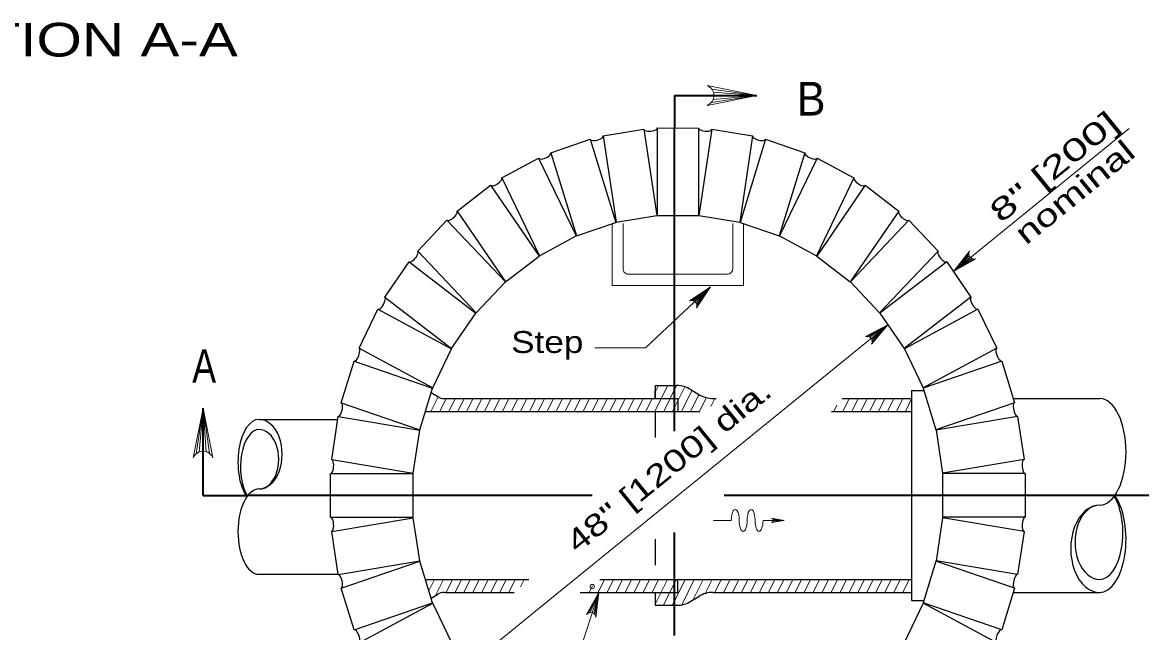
# Model space of a CAD drawing. Extents: x 1083.1 to 1117.1, y 697.4 to 741.4.
# Drawn here: x 1090.06 to 1098.04, y 723.17 to 727.52 of the extents above; entities that cross this region are included whole.
import ezdxf
from ezdxf.enums import TextEntityAlignment as Align

# ---------------------------------------------------------------- set-up
doc = ezdxf.new("R2010")
doc.units = 0
doc.header["$LTSCALE"] = 0.062
doc.header["$PDMODE"] = 32
doc.header["$PDSIZE"] = 0.031
doc.linetypes.add('MEDIUM_DASHED', pattern=[4.5, 3, -1.5])
doc.layers.add('1', color=7, linetype='Continuous', lineweight=13)

msp = doc.modelspace()

# ---------------------------------------------------------------- linework, layer by layer
at = {"layer": '1', "lineweight": 35}
for p, q in [((1094.71067, 727.00183), (1095.298, 727.00183)), ((1094.71067, 727.00183), (1094.71067, 726.76967)), ((1094.71067, 725.25758), (1094.71067, 726.76967)), ((1094.71067, 724.60558), (1094.71067, 725.25758)), ((1091.34783, 724.14683), (1091.34783, 724.76867)), ((1091.34783, 724.14683), (1091.66758, 724.14683)), ((1094.1245, 724.14683), (1091.66758, 724.14683)), ((1097.85225, 724.14683), (1095.0655, 724.14683)), ((1098.167, 724.14683), (1097.85225, 724.14683)), ((1094.71067, 723.14725), (1094.71067, 723.88192))]:
    msp.add_line(p, q, dxfattribs=at)
at = {"layer": '1'}
for p, q in [((1094.97367, 726.95225), (1095.298, 727.00183)), ((1094.9775, 727.04667), (1095.298, 727.00183)), ((1094.986, 726.97308), (1095.298, 727.00183)), ((1094.98833, 727.0245), (1095.298, 727.00183)), ((1094.99167, 727.00183), (1095.298, 727.00183)), ((1097.95358, 726.76517), (1096.70342, 725.74808)), ((1094.267, 725.64442), (1094.267, 726.08758)), ((1094.34383, 725.76575), (1094.34383, 726.08758)), ((1095.12658, 725.76575), (1095.12658, 726.08758)), ((1095.2035, 725.64442), (1095.2035, 726.08758)), ((1096.81108, 725.86867), (1096.70317, 725.74808)), ((1096.81408, 725.85667), (1096.70317, 725.74808)), ((1096.82017, 725.84692), (1096.70317, 725.74808)), ((1096.83158, 725.83775), (1096.70317, 725.74808)), ((1096.843, 725.83375), (1096.70317, 725.74808)), ((1094.38158, 725.72575), (1095.08883, 725.72575)), ((1094.267, 725.64442), (1095.2035, 725.64442)), ((1094.83525, 725.53908), (1094.96783, 725.63575)), ((1094.84692, 725.53608), (1094.96783, 725.63575)), ((1094.85908, 725.52783), (1094.96783, 725.63575)), ((1094.86592, 725.51858), (1094.96783, 725.63575)), ((1094.86983, 725.50692), (1094.96783, 725.63575)), ((1096.23242, 725.36483), (1095.51958, 724.78492)), ((1096.091, 725.28175), (1096.23242, 725.36483)), ((1096.10233, 725.27758), (1096.23242, 725.36483)), ((1096.11358, 725.26817), (1096.23242, 725.36483)), ((1096.11942, 725.25833), (1096.23242, 725.36483)), ((1096.12225, 725.24633), (1096.23242, 725.36483)), ((1094.66, 724.92983), (1094.56975, 724.74675)), ((1094.5965, 724.9305), (1094.57342, 724.88375)), ((1094.72458, 724.93125), (1094.63367, 724.74675)), ((1094.78417, 724.92242), (1094.69758, 724.74675)), ((1093.024, 724.851), (1092.97267, 724.74675)), ((1093.08192, 724.83883), (1093.03658, 724.74675)), ((1093.14583, 724.83883), (1093.10042, 724.74675)), ((1093.20975, 724.83883), (1093.16433, 724.74675)), ((1093.27358, 724.83883), (1093.22817, 724.74675)), ((1093.3375, 724.83883), (1093.29208, 724.74675)), ((1093.40133, 724.83883), (1093.356, 724.74675)), ((1093.46525, 724.83883), (1093.41983, 724.74675)), ((1093.52917, 724.83883), (1093.48375, 724.74675)), ((1093.593, 724.83883), (1093.54758, 724.74675)), ((1093.65692, 724.83883), (1093.6115, 724.74675)), ((1093.72083, 724.83883), (1093.67542, 724.74675)), ((1093.78467, 724.83883), (1093.73925, 724.74675)), ((1093.84858, 724.83883), (1093.80317, 724.74675)), ((1093.91242, 724.83883), (1093.86708, 724.74675)), ((1093.97633, 724.83883), (1093.93092, 724.74675)), ((1094.04025, 724.83883), (1093.99483, 724.74675)), ((1094.10408, 724.83883), (1094.05867, 724.74675)), ((1094.168, 724.83883), (1094.12258, 724.74675)), ((1094.23192, 724.83883), (1094.1865, 724.74675)), ((1094.29575, 724.83883), (1094.25033, 724.74675)), ((1094.35967, 724.83883), (1094.31425, 724.74675)), ((1094.4235, 724.83883), (1094.37817, 724.74675)), ((1094.48742, 724.83883), (1094.442, 724.74675)), ((1094.55133, 724.83883), (1094.50592, 724.74675)), ((1094.8355, 724.89708), (1094.76142, 724.74675)), ((1094.88492, 724.86767), (1094.82533, 724.74675)), ((1094.93742, 724.8445), (1094.88917, 724.74675)), ((1094.9985, 724.83883), (1094.9705, 724.78208)), ((1095.95675, 724.83883), (1095.91133, 724.74675)), ((1096.02067, 724.83883), (1095.97525, 724.74675)), ((1096.0845, 724.83883), (1096.03917, 724.74667)), ((1096.14842, 724.83883), (1096.103, 724.74667)), ((1096.21233, 724.83883), (1096.16692, 724.74675)), ((1096.27617, 724.83883), (1096.23075, 724.74675)), ((1096.34008, 724.83883), (1096.29467, 724.74675)), ((1096.40283, 724.8365), (1096.35858, 724.74675)), ((1091.29825, 724.44442), (1091.34783, 724.76867)), ((1091.319, 724.45667), (1091.34783, 724.76867)), ((1091.34783, 724.46233), (1091.34783, 724.76867)), ((1091.3705, 724.459), (1091.34783, 724.76867)), ((1091.39267, 724.44817), (1091.34783, 724.76867)), ((1095.51958, 724.78492), (1093.71942, 723.32042)), ((1095.86925, 724.791), (1095.8475, 724.74675)), ((1095.11617, 723.96858), (1094.99, 723.96858)), ((1095.49275, 723.96858), (1095.34233, 723.96858)), ((1095.49275, 723.96858), (1095.40208, 723.98458)), ((1095.49275, 723.96858), (1095.40208, 723.95258)), ((1095.49275, 723.96858), (1095.41175, 723.95858)), ((1095.49275, 723.96858), (1095.412, 723.97825)), ((1095.49275, 723.96858), (1095.41217, 723.97825)), ((1095.49275, 723.96858), (1095.41442, 723.97292)), ((1095.41458, 723.96475), (1095.49117, 723.96833)), ((1092.95892, 723.466), (1092.99883, 723.547)), ((1093.00583, 723.43158), (1093.06275, 723.547)), ((1093.08117, 723.45483), (1093.12658, 723.547)), ((1093.14508, 723.45483), (1093.1905, 723.547)), ((1093.209, 723.45483), (1093.25433, 723.547)), ((1093.27283, 723.45483), (1093.31825, 723.547)), ((1093.33675, 723.45483), (1093.38217, 723.547)), ((1093.40067, 723.45483), (1093.446, 723.547)), ((1093.4645, 723.45483), (1093.50992, 723.547)), ((1093.52842, 723.45483), (1093.57383, 723.547)), ((1093.61175, 723.49433), (1093.63767, 723.547)), ((1094.10333, 723.45483), (1094.12375, 723.49617)), ((1094.16725, 723.45483), (1094.21267, 723.547)), ((1094.23117, 723.45483), (1094.2765, 723.547)), ((1094.295, 723.45483), (1094.34042, 723.547)), ((1094.35892, 723.45483), (1094.40433, 723.547)), ((1094.42275, 723.45483), (1094.46817, 723.547)), ((1094.48667, 723.45483), (1094.53208, 723.547)), ((1094.55058, 723.45483), (1094.59592, 723.547)), ((1094.57317, 723.37117), (1094.65983, 723.547)), ((1094.63317, 723.36317), (1094.72375, 723.547)), ((1094.69683, 723.36283), (1094.78758, 723.547)), ((1094.76283, 723.36708), (1094.8515, 723.547)), ((1094.84442, 723.403), (1094.91542, 723.547)), ((1094.93208, 723.45125), (1094.97925, 723.547)), ((1094.99775, 723.45483), (1095.04317, 723.547)), ((1095.06167, 723.45483), (1095.107, 723.547)), ((1095.1255, 723.45483), (1095.17092, 723.547)), ((1095.18942, 723.45483), (1095.23483, 723.547)), ((1095.25333, 723.45483), (1095.29867, 723.547)), ((1095.31717, 723.45483), (1095.36258, 723.547)), ((1095.38108, 723.45483), (1095.4265, 723.547)), ((1095.44492, 723.45483), (1095.49033, 723.547)), ((1095.50883, 723.45483), (1095.55425, 723.547)), ((1095.57275, 723.45483), (1095.61808, 723.547)), ((1095.63658, 723.45483), (1095.682, 723.547)), ((1095.7005, 723.45483), (1095.74592, 723.547)), ((1095.76433, 723.45483), (1095.80975, 723.547)), ((1095.82825, 723.45483), (1095.87367, 723.547)), ((1095.89217, 723.45483), (1095.9375, 723.547)), ((1095.956, 723.45483), (1096.00142, 723.547)), ((1096.01992, 723.45483), (1096.06533, 723.547)), ((1096.08383, 723.45483), (1096.12917, 723.547)), ((1096.14767, 723.45483), (1096.19308, 723.547)), ((1096.21158, 723.45483), (1096.257, 723.547)), ((1096.27542, 723.45483), (1096.32083, 723.547)), ((1096.33933, 723.45483), (1096.38475, 723.547)), ((1094.09825, 723.3085), (1094.17225, 723.45483)), ((1094.11, 723.31108), (1094.17225, 723.45483)), ((1094.12458, 723.30933), (1094.17225, 723.45483)), ((1094.13483, 723.30425), (1094.17225, 723.45483)), ((1094.14367, 723.29558), (1094.17225, 723.45483)), ((1093.71942, 723.32042), (1093.23758, 722.92842))]:
    msp.add_line(p, q, dxfattribs=at)
at = {"layer": '1', "lineweight": 25}
for p, q in [((1094.20217, 726.71292), (1094.49317, 726.76175)), ((1094.49317, 726.76175), (1094.58533, 726.14558)), ((1094.58792, 726.76967), (1094.58792, 726.14583)), ((1094.58792, 726.76967), (1094.88258, 726.76958)), ((1094.88258, 726.76958), (1094.8825, 726.14583)), ((1094.97725, 726.76175), (1094.88508, 726.14558)), ((1094.97725, 726.76175), (1095.26825, 726.71292)), ((1093.82958, 726.59308), (1094.10983, 726.68942)), ((1094.10983, 726.68942), (1094.29192, 726.09617)), ((1094.20217, 726.71292), (1094.29442, 726.09675)), ((1095.26825, 726.71292), (1095.17608, 726.09683)), ((1095.36067, 726.6895), (1095.17858, 726.09617)), ((1095.36067, 726.6895), (1095.64092, 726.59308)), ((1093.82958, 726.59308), (1094.01167, 725.99975)), ((1095.64092, 726.59308), (1095.45875, 725.99975)), ((1093.47933, 726.413), (1093.74183, 726.55458)), ((1093.74183, 726.55458), (1094.00933, 725.99875)), ((1095.72867, 726.55458), (1095.46117, 725.99875)), ((1095.72867, 726.55458), (1095.99117, 726.41292)), ((1093.15992, 726.17708), (1093.39825, 726.36042)), ((1093.39825, 726.36042), (1093.74458, 725.85567)), ((1093.47933, 726.413), (1093.74683, 725.85708)), ((1095.99117, 726.41292), (1095.72367, 725.85717)), ((1096.07217, 726.36042), (1095.72583, 725.85567)), ((1096.07217, 726.36042), (1096.31058, 726.17708)), ((1092.87933, 725.89117), (1093.08767, 726.11175)), ((1093.08767, 726.11175), (1093.50433, 725.67058)), ((1093.15992, 726.17708), (1093.50625, 725.67233)), ((1094.29442, 726.09675), (1094.58533, 726.14558)), ((1094.58792, 726.14583), (1094.8825, 726.14583)), ((1094.88508, 726.14558), (1095.17608, 726.09683)), ((1096.31058, 726.17708), (1095.96417, 725.67233)), ((1096.38283, 726.11175), (1095.96617, 725.67058)), ((1096.38283, 726.11175), (1096.59117, 725.89117)), ((1094.01167, 725.99975), (1094.29192, 726.09617)), ((1095.17858, 726.09617), (1095.45875, 725.99975)), ((1093.74683, 725.85708), (1094.00933, 725.99875)), ((1095.46117, 725.99875), (1095.72367, 725.85717)), ((1092.87933, 725.89117), (1093.296, 725.45008)), ((1096.59117, 725.89117), (1096.1745, 725.45008)), ((1092.64442, 725.56233), (1092.81767, 725.81467)), ((1092.81767, 725.81467), (1093.29433, 725.448)), ((1093.50625, 725.67233), (1093.74458, 725.85567)), ((1095.72583, 725.85567), (1095.96417, 725.67233)), ((1096.65283, 725.81467), (1096.17617, 725.448)), ((1096.65283, 725.81467), (1096.826, 725.56233)), ((1093.296, 725.45008), (1093.50433, 725.67058)), ((1095.96617, 725.67058), (1096.1745, 725.45008)), ((1092.64442, 725.56233), (1093.12117, 725.19567)), ((1096.826, 725.56233), (1096.34933, 725.19567)), ((1092.46108, 725.19858), (1092.59483, 725.4765)), ((1092.59483, 725.4765), (1093.11983, 725.19333)), ((1096.87567, 725.4765), (1096.35067, 725.19333)), ((1096.87567, 725.4765), (1097.00942, 725.19858)), ((1093.12117, 725.19567), (1093.29433, 725.448)), ((1096.17617, 725.448), (1096.34933, 725.19567)), ((1092.46108, 725.19858), (1092.98608, 724.91542)), ((1092.98608, 724.91542), (1093.11983, 725.19333)), ((1096.35067, 725.19333), (1096.48442, 724.91542)), ((1097.00942, 725.19858), (1096.48442, 724.91542)), ((1092.33367, 724.809), (1092.42467, 725.10567)), ((1092.42467, 725.10567), (1092.98508, 724.91292)), ((1097.04575, 725.10567), (1096.48542, 724.91292)), ((1097.04575, 725.10567), (1097.13683, 724.809)), ((1092.894, 724.61625), (1092.98508, 724.91292)), ((1094.57342, 724.931), (1094.72592, 724.931)), ((1094.57342, 724.931), (1094.57342, 724.83883)), ((1096.48542, 724.91292), (1096.57642, 724.61625)), ((1092.97525, 724.88083), (1093.022, 724.85225)), ((1093.06917, 724.83883), (1094.73525, 724.83883)), ((1094.57342, 724.83883), (1094.57342, 724.89692)), ((1094.73525, 724.83883), (1094.73525, 724.74675)), ((1094.8285, 724.90208), (1094.88475, 724.86775)), ((1094.98733, 724.83883), (1095.00867, 724.83883)), ((1095.90758, 724.83883), (1096.40283, 724.83883)), ((1096.40283, 724.89692), (1096.40283, 723.39675)), ((1096.40283, 724.89692), (1096.49025, 724.89692)), ((1096.40283, 724.89692), (1096.49025, 724.89692)), ((1097.12767, 724.83883), (1097.74417, 724.83883)), ((1092.33367, 724.809), (1092.894, 724.61625)), ((1092.93408, 724.74675), (1094.89092, 724.74675)), ((1095.83058, 724.74675), (1096.40283, 724.74675)), ((1097.13683, 724.809), (1096.57642, 724.61625)), ((1091.74717, 724.68958), (1092.30825, 724.68958)), ((1092.26533, 724.40308), (1092.3115, 724.71117)), ((1092.3115, 724.71117), (1092.89342, 724.61358)), ((1097.159, 724.71117), (1096.577, 724.61358)), ((1097.159, 724.71117), (1097.20508, 724.40308)), ((1092.84733, 724.3055), (1092.89342, 724.61358)), ((1096.577, 724.61358), (1096.62308, 724.3055)), ((1092.26533, 724.40308), (1092.84733, 724.3055)), ((1097.20508, 724.40308), (1096.62308, 724.3055)), ((1092.25792, 723.99092), (1092.25792, 724.30283)), ((1092.25792, 724.30283), (1092.84717, 724.30283)), ((1092.84717, 723.99092), (1092.84717, 724.30283)), ((1097.21258, 724.30283), (1096.62333, 724.30283)), ((1096.62333, 724.30283), (1096.62333, 723.99092)), ((1097.21258, 724.30283), (1097.21258, 723.99092)), ((1092.25792, 723.99092), (1092.84717, 723.99092)), ((1092.26533, 723.89058), (1092.84733, 723.98817)), ((1092.89342, 723.68008), (1092.84733, 723.98817)), ((1096.62308, 723.98817), (1096.577, 723.68008)), ((1097.20508, 723.89058), (1096.62308, 723.98817)), ((1097.21258, 723.99092), (1096.62333, 723.99092)), ((1092.31142, 723.5825), (1092.26533, 723.89058)), ((1097.20508, 723.89058), (1097.159, 723.5825)), ((1092.31142, 723.5825), (1092.89342, 723.68008)), ((1092.33367, 723.48467), (1092.89408, 723.6775)), ((1092.98508, 723.38083), (1092.89408, 723.6775)), ((1096.57642, 723.6775), (1096.48542, 723.38083)), ((1097.13683, 723.48475), (1096.57642, 723.6775)), ((1097.159, 723.5825), (1096.577, 723.68008)), ((1091.74717, 723.58392), (1092.31125, 723.58392)), ((1092.42467, 723.18808), (1092.33367, 723.48467)), ((1092.93408, 723.547), (1093.67075, 723.547)), ((1094.17825, 723.547), (1096.40283, 723.547)), ((1094.73525, 723.45483), (1094.73525, 723.547)), ((1094.73525, 723.45483), (1094.73525, 723.547)), ((1097.13683, 723.48475), (1097.04575, 723.18808)), ((1092.97525, 723.41292), (1093.022, 723.4415)), ((1093.06917, 723.45483), (1093.5675, 723.45483)), ((1094.038, 723.45483), (1094.73525, 723.45483)), ((1094.57342, 723.45483), (1094.57342, 723.39675)), ((1094.57342, 723.45483), (1094.57342, 723.39675)), ((1094.57342, 723.45483), (1094.57342, 723.36275)), ((1094.8285, 723.39158), (1094.88475, 723.426)), ((1094.98733, 723.45483), (1096.40283, 723.45483)), ((1096.40283, 723.39675), (1096.49025, 723.39675)), ((1097.12767, 723.45483), (1097.74417, 723.45483)), ((1092.42467, 723.18808), (1092.98508, 723.38083)), ((1092.46108, 723.09508), (1092.98608, 723.37833)), ((1093.11983, 723.10042), (1092.98608, 723.37833)), ((1094.57342, 723.36275), (1094.72592, 723.36275)), ((1096.48442, 723.37833), (1096.35067, 723.10042)), ((1097.00942, 723.09508), (1096.48442, 723.37833)), ((1097.04575, 723.18808), (1096.48542, 723.38083))]:
    msp.add_line(p, q, dxfattribs=at)
at = {"layer": '1', "linetype": 'MEDIUM_DASHED', "lineweight": 25}
for p, q in [((1094.57342, 724.74675), (1094.57342, 724.49817)), ((1094.57342, 723.83508), (1094.57342, 723.547))]:
    msp.add_line(p, q, dxfattribs=at)
at = {"layer": '1'}
for points in [[(1094.944, 726.931), (1095.298, 727.00183), (1094.944, 727.07267)], [(1096.86125, 725.83525), (1096.70317, 725.74808), (1096.8155, 725.88933)], [(1094.96783, 725.63575), (1094.50367, 725.19975), (1094.14242, 725.19975)], [(1094.81725, 725.53617), (1094.96783, 725.63575), (1094.86708, 725.48592)], [(1096.07275, 725.28058), (1096.23242, 725.36483), (1096.11742, 725.22567)], [(1091.277, 724.41467), (1091.34783, 724.76867), (1091.41858, 724.41467)], [(1094.17225, 723.45483), (1093.47458, 721.3085), (1092.87242, 721.3085)], [(1094.0835, 723.29767), (1094.17225, 723.45483), (1094.15075, 723.27567)]]:
    msp.add_lwpolyline(points, dxfattribs=at)
for centre, radius, start, end in [((1094.91537, 727.00192), 0.0764, 292.08605, 67.91218), ((1096.84927, 725.87157), 0.0382, 152.27638, 288.10251), ((1094.83206, 725.50094), 0.0382, 336.86842, 112.69455), ((1096.08403, 725.24407), 0.0382, 331.21837, 107.04449), ((1091.34788, 724.38607), 0.0764, 22.08782, 157.91395), ((1094.11272, 723.27306), 0.0382, 3.94896, 139.77509)]:
    msp.add_arc(centre, radius, start, end, dxfattribs=at)
at = {"layer": '1', "lineweight": 25}
for centre, start, end in [((1094.72591, 724.73431), 58.56516, 90), ((1094.98733, 725.03552), 238.5654, 270), ((1094.72591, 723.5594), 269.99862, 301.43003), ((1094.98733, 723.2582), 90, 121.43151)]:
    msp.add_arc(centre, 0.19667, start, end, dxfattribs=at)
for centre, major_axis, ratio, start_param, end_param in [((1094.54057, 726.76568), (0.04736, 0.00403), 0.392063, 3.1374537, 6.2790464), ((1094.92992, 726.76568), (0.04736, -0.00402), 0.392063, 3.1457278, 6.2873205), ((1094.15601, 726.7012), (0.04614, 0.01196), 0.389745, 3.1296802, 6.2712729), ((1095.31448, 726.7012), (0.04614, -0.01196), 0.389747, 3.1535017, 6.2950944), ((1093.78571, 726.57382), (0.04376, 0.01956), 0.385425, 3.1233154, 6.2649081), ((1095.68477, 726.57382), (0.04376, -0.01956), 0.385427, 3.1598674, 6.3014601), ((1093.4388, 726.38668), (0.04029, 0.02663), 0.37966, 3.1190216, 6.2606142), ((1096.03169, 726.38668), (0.04029, -0.02663), 0.379662, 3.1641623, 6.3057549), ((1093.1238, 726.14439), (0.03583, 0.033), 0.373134, 3.117142, 6.2587347), ((1096.34668, 726.14438), (0.03584, -0.033), 0.373137, 3.166043, 6.3076357), ((1092.84849, 725.85291), (0.03052, 0.03853), 0.366547, 3.1177098, 6.2593025), ((1096.62199, 725.8529), (0.03053, -0.03852), 0.36655, 3.1654763, 6.307069), ((1092.61963, 725.51943), (0.0245, 0.04308), 0.360527, 3.1205104, 6.2621031), ((1096.85085, 725.51942), (0.0245, -0.04308), 0.360529, 3.1626767, 6.3042693), ((1092.44287, 725.15214), (0.01791, 0.04658), 0.355581, 3.1251606, 6.2667532), ((1097.02761, 725.15213), (0.01791, -0.04658), 0.355583, 3.1580272, 6.2996199), ((1093.0692, 724.93879), (0, -0.09994), 0.944544, 5.7595819, 6.2831851), ((1097.74416, 724.45826), (0, -0.3806), 0.493973, 6.2831853, 9.4247779), ((1092.32255, 724.76011), (0.01091, 0.04895), 0.352085, 3.1311777, 6.2727704), ((1097.14793, 724.7601), (0.01091, -0.04895), 0.352086, 3.1520106, 6.2936033), ((1091.74713, 724.3851), (0, 0.30449), 0.493973, 6.2831853, 8.8076526), ((1091.74713, 724.44126), (0, 0.24833), 0.663452, 3.1415925, 6.2831852), ((1091.74714, 724.34986), (0, 0.26763), 0.493973, 6.2831853, 8.7432897), ((1091.74713, 724.40521), (0, 0.21228), 0.663452, 3.1415925, 6.2831852), ((1092.26164, 724.35297), (0.00366, 0.05015), 0.350278, 3.1380288, 6.2796215), ((1097.20883, 724.35296), (0.00367, -0.05015), 0.350278, 3.1451597, 6.2867524), ((1091.74713, 723.88844), (0, 0.30449), 0.493973, 6.2831853, 9.4247779), ((1097.74416, 723.83546), (0, -0.3806), 0.493973, 6.2831853, 8.8122226), ((1097.74416, 723.88152), (0, -0.33452), 0.493973, 6.2831853, 8.7432884), ((1097.74416, 723.76626), (0, -0.3114), 0.663452, 3.1415925, 6.2831852), ((1097.74416, 723.81233), (0, -0.26533), 0.663452, 3.1415925, 6.2831852), ((1092.26164, 723.94076), (-0.00367, 0.05015), 0.350278, 3.1451597, 6.2867524), ((1097.20883, 723.94075), (-0.00366, -0.05015), 0.350278, 3.1380288, 6.2796215), ((1092.32255, 723.53362), (-0.01091, 0.04895), 0.352086, 3.1520106, 6.2936033), ((1097.14792, 723.53361), (-0.01091, -0.04895), 0.352085, 3.1311777, 6.2727704), ((1093.0692, 723.35492), (0, 0.09994), 0.944544, 0.0000001, 0.5236033), ((1092.44287, 723.14158), (-0.01791, 0.04658), 0.355583, 3.1580272, 6.2996199), ((1097.02761, 723.14157), (-0.01791, -0.04658), 0.355581, 3.1251606, 6.2667532)]:
    msp.add_ellipse(centre, major_axis=major_axis, ratio=ratio, start_param=start_param, end_param=end_param, dxfattribs=at)
at = {"layer": '1'}
for centre, major_axis, ratio, start_param, end_param in [((1094.38162, 725.76572), (0, 0.03998), 0.944544, 1.5707911, 3.141593), ((1095.08886, 725.76572), (0, -0.03998), 0.944544, 6.2831847, 7.8539765), ((1095.14445, 723.9686), (0, -0.07867), 0.359358, 1.5707963, 4.712389), ((1095.25754, 723.9686), (0, -0.07867), 0.359358, 1.5707963, 4.712389), ((1095.20099, 723.9686), (0, -0.07867), 0.359358, 4.712389, 7.8539816), ((1095.31408, 723.9686), (0, -0.07867), 0.359358, 4.712389, 7.8539816), ((1095.39973, 723.96861), (0, -0.01618), 0.944544, 0.1533668, 2.9873365)]:
    msp.add_ellipse(centre, major_axis=major_axis, ratio=ratio, start_param=start_param, end_param=end_param, dxfattribs=at)
msp.add_point((1094.12375, 723.49617), dxfattribs=at)

# ---------------------------------------------------------------- texts
for s, height, width, p in [('SECTION A-A', 0.24, 1.3, (1088.9305, 727.28)), ('B', 0.24, 0.95, (1095.58458, 726.8585)), ('Step', 0.156, 1.2, (1093.54567, 725.164)), ('A', 0.24, 0.8, (1091.26992, 724.95092))]:
    msp.add_text(s, height=height, dxfattribs=dict(at, width=width)).set_placement(p)
for s, width, p in [('8" [200]', 1.55, (1097.46715, 726.43322)), ('nominal', 1.4, (1097.61486, 726.25172))]:
    msp.add_text(s, height=0.156, rotation=39.13, dxfattribs=dict(at, width=width)).set_placement(p, align=Align.CENTER)
at = {"layer": '1', "width": 1.35}
msp.add_text('48" [1200] dia.', height=0.156, rotation=39.13, dxfattribs=at).set_placement((1094.01742, 723.7285))

doc.saveas('drawing.dxf')
